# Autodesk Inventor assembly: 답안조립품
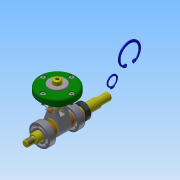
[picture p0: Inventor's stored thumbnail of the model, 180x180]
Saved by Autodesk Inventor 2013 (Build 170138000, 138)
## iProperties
Created: 2016-08
Part Number: 답안조립품
Document SubType Name: Assembly
Designer: Administrator
Author: Administrator
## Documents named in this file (18)
- C:\Users\Administrator\Desktop\460808V1001\답안조립품.iam
- C:\Users\Administrator\Desktop\460808V1001\본체.ipt
- C:\Users\Administrator\Desktop\460808V1001\사이드 커버.ipt
- 사이드 커버.ipt
- C:\Users\Administrator\Desktop\460808V1001\탑 부시.ipt
- C:\Users\Administrator\Desktop\460808V1001\탑 커버.ipt
- 탑 커버.ipt
- C:\Users\Administrator\Desktop\460808V1001\볼트 M4 x 12.ipt
- C:\Users\Administrator\Desktop\460808V1001\오일 실 15 25 7.ipt
- C:\Users\Administrator\Desktop\460808V1001\편심축.ipt
- C:\Users\Administrator\Desktop\460808V1001\링크.ipt
- C:\Users\Administrator\Desktop\460808V1001\클래스터 핀 6 x 24.ipt
- C:\Users\Administrator\Desktop\460808V1001\분할핀 1.6 x 12.ipt
- C:\Users\Administrator\Desktop\460808V1001\부시1.ipt
- C:\Users\Administrator\Desktop\460808V1001\슬라이더.ipt
- C:\Users\Administrator\Desktop\460808V1001\베어링 15 x 35 x 11.ipt
- C:\Users\Administrator\Desktop\460808V1001\멈춤링 15 x 1.ipt
- C:\Users\Administrator\Desktop\460808V1001\멈춤링 35x1.6.ipt
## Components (4 placed, 1 different names)
1. ISO 4762 M4 x 12:1
2. ISO 4762 M4 x 12:2
3. ISO 4762 M4 x 12:3
4. ISO 4762 M4 x 12:4
